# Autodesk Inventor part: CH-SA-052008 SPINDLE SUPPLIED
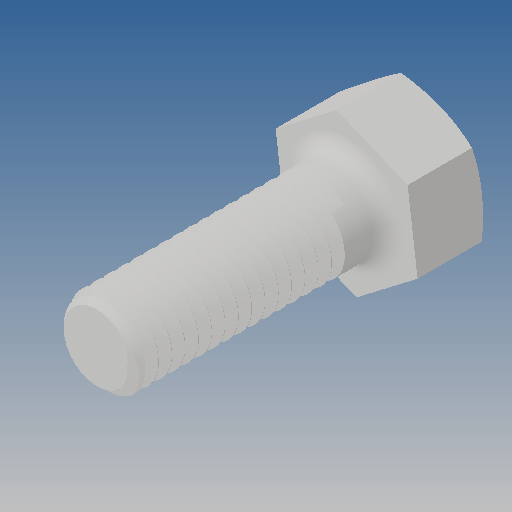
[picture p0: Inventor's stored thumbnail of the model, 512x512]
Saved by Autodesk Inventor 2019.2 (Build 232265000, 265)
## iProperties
Created: 2013-03
Part Number: CH-SA-052008 SPINDLE SUPPLIED
Material: Ogólny
Document SubType Name: Modeling
Designer: CADENGINEERING4
Density: 1 g/cm^3
Appearance: Domyślna
Author: CADENGINEERING4
Revision Number: ÈÎºÎ
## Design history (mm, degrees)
feature "ÇÐ³ý-É¨Ãè2"
node "Bryła1"
